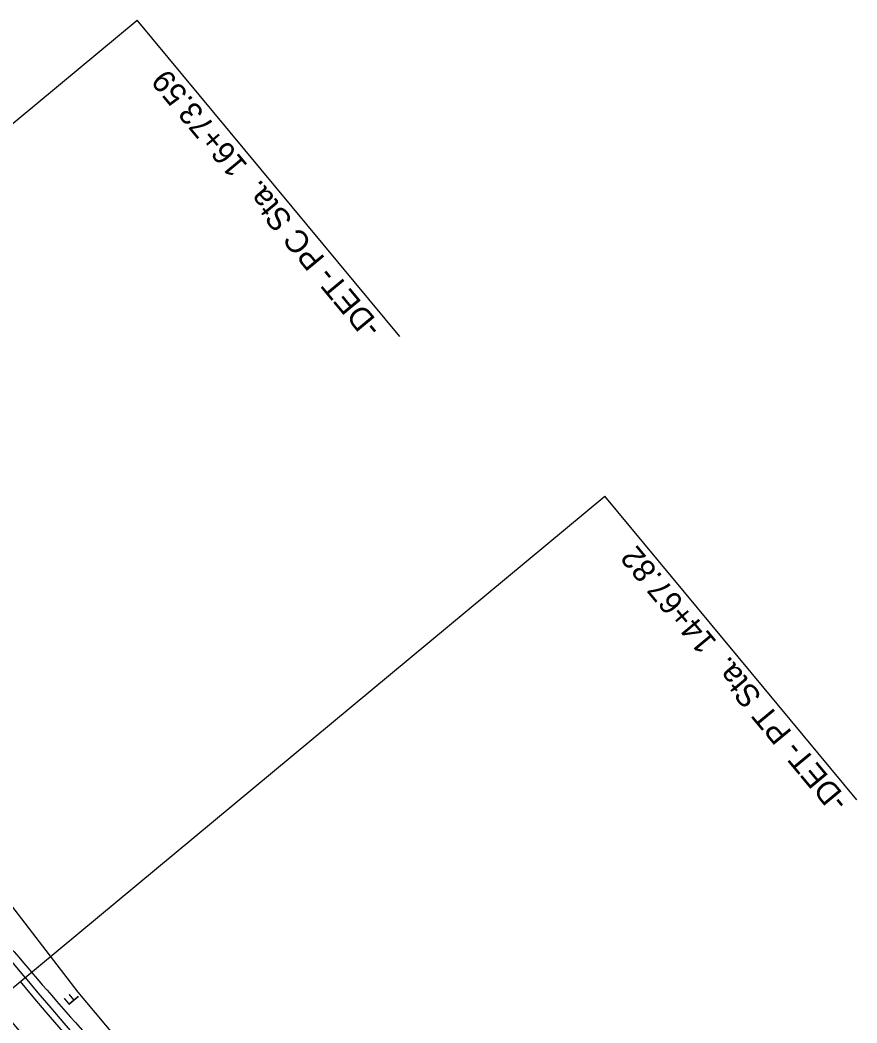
# Model space of a CAD drawing. Extents: x 2597390 to 2598563, y 852595 to 853909.
# Drawn here: x 2598069.2 to 2598328.1, y 853159.2 to 853469.5 of the extents above; entities that cross this region are included whole.
import ezdxf

# ---------------------------------------------------------------- set-up
doc = ezdxf.new("R2010")
doc.units = 0
for name, color, linetype in [('Prop EOT', 7, 'Continuous'), ('Prop Guardrail Temporary', 7, 'Continuous'), ('Prop Horizontal Alignment', 7, 'Continuous'), ('Prop Horizontal Alignment Station Label', 7, 'Continuous'), ('Prop Paved Shoulder', 7, 'Continuous'), ('Prop SS Fill Line', 7, 'Continuous'), ('Prop SS Misc', 7, 'Continuous')]:
    doc.layers.add(name, color=color, linetype=linetype)

msp = doc.modelspace()

# ---------------------------------------------------------------- linework, layer by layer
at = {"layer": 'Prop EOT'}
msp.add_arc((2598702.35, 853697.75), 823, 219.70669, 233.47068, dxfattribs=at)
at = {"layer": 'Prop Guardrail Temporary'}
for centre, radius, start, end in [((2601230.03, 855890.15), 4164.27, 219.90413, 220.88881), ((2598696.5, 853703.86), 817.85, 221.28346, 226.23325)]:
    msp.add_arc(centre, radius, start, end, dxfattribs=at)
at = {"layer": 'Prop Horizontal Alignment'}
msp.add_arc((2598702.35, 853697.75), 833, 219.70669, 233.47068, dxfattribs=at)
at = {"layer": 'Prop Horizontal Alignment Station Label'}
for p, q in [((2597931.2, 853324.84), (2598105.41, 853469.51)), ((2598186.75, 853371.55), (2598105.41, 853469.51)), ((2598062.66, 853166.54), (2598250.11, 853322.2)), ((2598328.13, 853228.25), (2598250.11, 853322.2))]:
    msp.add_line(p, q, dxfattribs=at)
at = {"layer": 'Prop Paved Shoulder'}
msp.add_line((2598070.73, 853173.24), (2598022.02, 853231.9), dxfattribs=at)
msp.add_arc((2598702.35, 853697.75), 821, 219.70669, 233.47068, dxfattribs=at)
at = {"layer": 'Prop SS Fill Line'}
for p, q in [((2598087.2, 853168.72), (2598056.63, 853208.32)), ((2598119.31, 853130.39), (2598087.2, 853168.72))]:
    msp.add_line(p, q, dxfattribs=at)

# ---------------------------------------------------------------- texts
at = {"layer": 'Prop Horizontal Alignment Station Label'}
for s, p in [('-DET- PC Sta.  16+73.59', (2598181.41, 853374.55)), ('-DET- PT Sta.  14+67.82', (2598325.89, 853227.91))]:
    msp.add_text(s, height=7, rotation=129.7067, dxfattribs=at).set_placement(p)
at = {"layer": 'Prop SS Misc'}
msp.add_text('F', height=4, rotation=129.7067, dxfattribs=at).set_placement((2598087.72, 853166.9))

doc.saveas('drawing.dxf')
